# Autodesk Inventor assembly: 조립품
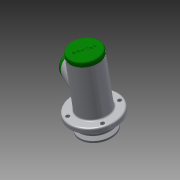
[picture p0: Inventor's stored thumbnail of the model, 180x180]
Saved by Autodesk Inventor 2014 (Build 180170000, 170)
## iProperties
Created: 2016-08
Part Number: 조립품
Document SubType Name: Assembly
Designer: 703-04
Author: 703-04
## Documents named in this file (25)
- C:\Users\703-04\Desktop\460808V1019\조립품.iam
- C:\Users\703-04\Desktop\460808V1019\본체.ipt
- C:\Users\703-04\Desktop\460808V1019\V-벨트풀리.ipt
- C:\Users\703-04\Desktop\460808V1019\너트 M10.ipt
- C:\Users\703-04\Desktop\460808V1019\링크.ipt
- C:\Users\703-04\Desktop\460808V1019\멈춤링 15 x 1.ipt
- C:\Users\703-04\Desktop\460808V1019\멈춤링 35x1.6.ipt
- C:\Users\703-04\Desktop\460808V1019\베어링 15 x 35 x 11.ipt
- C:\Users\703-04\Desktop\460808V1019\볼트 M4 x 10.ipt
- C:\Users\703-04\Desktop\460808V1019\볼트 M4 x 12.ipt
- C:\Users\703-04\Desktop\460808V1019\부시1.ipt
- C:\Users\703-04\Desktop\460808V1019\부시2.ipt
- C:\Users\703-04\Desktop\460808V1019\분할핀 1.6 x 12.ipt
- C:\Users\703-04\Desktop\460808V1019\사이드 커버.ipt
- 사이드 커버.ipt
- C:\Users\703-04\Desktop\460808V1019\슬라이더.ipt
- C:\Users\703-04\Desktop\460808V1019\오일 실 15 25 7.ipt
- C:\Users\703-04\Desktop\460808V1019\와셔 4x16.ipt
- C:\Users\703-04\Desktop\460808V1019\와셔 10x21.ipt
- C:\Users\703-04\Desktop\460808V1019\클래스터 핀 6 x 24.ipt
- C:\Users\703-04\Desktop\460808V1019\키 4 x 4 x 18.ipt
- C:\Users\703-04\Desktop\460808V1019\탑 부시.ipt
- C:\Users\703-04\Desktop\460808V1019\탑 커버.ipt
- 탑 커버.ipt
- C:\Users\703-04\Desktop\460808V1019\편심축.ipt
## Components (6 placed, 3 different names)
1. V-벨트풀리:1
2. ISO 4017 M4 x 10:1
3. ISO 4762 M4 x 12:1
4. ISO 4762 M4 x 12:2
5. ISO 4762 M4 x 12:3
6. ISO 4762 M4 x 12:4
